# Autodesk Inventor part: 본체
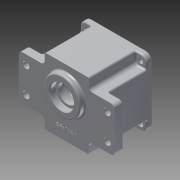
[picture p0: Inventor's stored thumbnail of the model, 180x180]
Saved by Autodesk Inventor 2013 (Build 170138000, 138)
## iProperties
Created: 2015-07
Part Number: 본체
Material: 알루미늄 6061
Document SubType Name: Modeling
Designer: user
Density: 2.71 g/cm^3
Mass: 705.36 g
Surface Area: 672.936 cm^2
Volume: 260.28 cm^3
Author: user
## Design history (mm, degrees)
sketch "스케치1"
  geometry: L1 (65, -30)-(-65, -30); L2 (-65, -30)-(-65, 30); L3 (-65, 30)-(65, 30); L4 (65, 30)-(65, -30); L5 (65, -30)-(-65, 30); L6 (-65, -30)-(65, 30); L7 (45, -45)-(-45, -45); L8 (-45, -45)-(-45, 45); L9 (-45, 45)-(45, 45); L10 (45, 45)-(45, -45); L11 (45, -45)-(-45, 45); L12 (-45, -45)-(45, 45); 1 further point
  constraints: 24 end point, 4 midpoint, 4 parallel, 2 horizontal, 2 perpendicular
  dimensions: "d0" = 130 distance of L2.end L3.end; "d1" = 60 distance of L1.end L2.end; "d2" = 90 distance of L8.end L9.end; "d3" = 90 distance of L7.end L8.end
extrude "돌출1" new body sketch "스케치1" distance "d4" = 12; taper "d5" = 0 deg
sketch "스케치2"
  geometry: L1 (45, -45)-(-45, -45); L2 (-45, -45)-(-45, 45); L3 (-45, 45)-(45, 45); L4 (45, 45)-(45, -45); L5 (45, -45)-(-45, 45); L6 (-45, -45)-(45, 45); 1 further point
  constraints: 12 end point, 2 midpoint, 2 parallel, 1 horizontal, 1 perpendicular
  dimensions: "d6" = 90 distance of L2.end L3.end (derived); "d7" = 90 distance of L1.end L2.end (derived)
extrude "돌출2" join sketch "스케치2" distance "d8" = 58; taper "d9" = 0 deg
sketch "스케치3"
  geometry: L1 (45, 30)-(45, 45) reference; L2 (45, 45)-(-45, 45) reference; L3 (-45, 45)-(-45, 30) reference; L4 (-45, -30)-(-45, -45) reference; L5 (30, -30)-(-30, -30); L6 (-30, -30)-(-30, 30); L7 (-30, 30)-(30, 30); L8 (30, 30)-(30, -30); L9 (30, -30)-(-30, 30); L10 (-30, -30)-(30, 30); L11 (-30, 30)-(-45, 30); L12 (30, 30)-(45, 30); L13 (30, 30)-(30, 45); L14 (-30, 30)-(-30, 45); L15 (-30, 45)-(-45, 45); L16 (-45, 30)-(-45, 45); L17 (30, 45)-(45, 45); L18 (45, 45)-(45, 30); L19 (0, 0)-(41.753, 0); L20 (-30, -30)-(-30, -45); L21 (-30, -30)-(-45, -30); L22 (-45, -30)-(-45, -45); L23 (-30, -45)-(-45, -45); L24 (30, -45)-(45, -45); L25 (30, -30)-(30, -45); L26 (30, -30)-(45, -30); L27 (45, -45)-(45, -30)
  constraints: 46 end point, 6 perpendicular, 2 collinear, 2 midpoint, 2 parallel, 2 point on line, 2 symmetric about line, 1 horizontal
  dimensions: "d10" = 60 distance of L6.end L7.end; "d11" = 60 distance of L5.end L6.end
extrude "돌출3" cut sketch "스케치3" distance "d12" = 63; taper "d13" = 0 deg
sketch "스케치4"
  geometry: L1 (37, -37)-(-37, -37); L2 (-37, -37)-(-37, 37); L3 (-37, 37)-(37, 37); L4 (37, 37)-(37, -37); L5 (37, -37)-(-37, 37); L6 (-37, -37)-(37, 37); C1 r 3.5 at (-37, 37); C2 r 3.5 at (-37, -37); C3 r 3.5 at (37, -37); C4 r 3.5 at (37, 37); 1 further point
  constraints: 12 end point, 4 centre point, 2 midpoint, 2 parallel, 1 coincident, 1 horizontal, 1 perpendicular, 9 other
  dimensions: "d14" = 74 distance of L2.end L3.end; "d15" = 74 distance of L1.end L2.end; "d16" = 7 diameter of C1; "d19" = 360 deg dimension on point (0, 0) C1.centre (derived)
extrude "돌출4" cut sketch "스케치4" distance "d21" = 63; taper "d22" = 0 deg
fillet "모깎기1" dims "d23" = 8
fillet "모깎기2" dims "d24" = 8
sketch "스케치5"
  geometry: C1 r 40 at (0, 0); 1 further point
  constraints: 1 centre point, 1 coincident
  dimensions: "d25" = 80 diameter of C1
extrude "돌출5" cut sketch "스케치5" distance "d26" = 9; taper "d27" = 0 deg
sketch "스케치6"
  geometry: C1 r 40 at (0, 0) reference; C2 r 39 at (0, 0)
  constraints: 1 centre point, 1 coincident
  dimensions: "d28" = 78 diameter of C2
extrude "돌출6" cut sketch "스케치6" distance "d29" = 52; taper "d30" = 0 deg
sketch "스케치7"
  geometry: L1 (-65, -30)-(-30, -30) reference; L2 (0, 0)-(0, 11); C1 r 25 at (0, 11)
  constraints: 2 end point, 1 centre point, 1 coincident, 1 perpendicular
  dimensions: "d31" = 11 distance of L2.start L2.end; "d32" = 50 diameter of C1
extrude "돌출7" join sketch "스케치7" distance "d33" = 7; taper "d34" = 0 deg
sketch "스케치8"
  geometry: C1 r 25 at (0, 0) reference; C2 r 16 at (0, 0); 1 further point
  constraints: 1 centre point, 1 coincident
  dimensions: "d35" = 32 diameter of C2
extrude "돌출8" cut sketch "스케치8" distance "d36" = 8; taper "d37" = 0 deg
sketch "스케치9"
  geometry: L1 (0, 0)-(0, -11); L2 (0, 0)-(0, 20); C1 r 39 at (0, 0) reference; A1 r 20.5 centre (0, -11) between (-7.402, 8.117) and (7.402, 8.117); A2 r 14 centre (0, 20) between (7.402, 8.117) and (-7.402, 8.117)
  constraints: 4 end point, 4 point on circle, 2 centre point, 1 coincident, 1 collinear, 1 vertical
  dimensions: "d38" = 11 distance of L1.start L1.end; "d39" = 41 diameter of A1; "d40" = 20 distance of L1.start L2.end; "d41" = 28 diameter of A2; "d42" = 7.40221 distance from line of A1.end L1; "d43" = 0 distance from line of A2.centre L1
extrude "돌출9" join sketch "스케치9" distance "d44" = 7; taper "d45" = 0 deg
sketch "스케치10"
  geometry: C1 r 16 at (0, 0) reference; C2 r 12.5 at (0, 0); 1 further point
  constraints: 1 centre point, 1 coincident
  dimensions: "d46" = 25 diameter of C2
extrude "돌출10" cut sketch "스케치10" distance "d47" = 5; taper "d48" = 0 deg
sketch "스케치11"
  geometry: C1 r 12.5 at (0, 0) reference; C2 r 17.5 at (0, 0); 1 further point
  constraints: 1 centre point, 1 coincident
  dimensions: "d49" = 35 diameter of C2
extrude "돌출11" cut sketch "스케치11" distance "d50" = 10; taper "d51" = 0 deg
sketch "스케치12"
  geometry: C1 r 11 at (0, 20); A1 r 14 centre (0, 20) between (7.402, 8.117) and (-7.402, 8.117) reference; 1 further point
  constraints: 1 centre point, 1 coincident
  dimensions: "d52" = 22 diameter of C1
extrude "돌출12" cut sketch "스케치12" distance "d53" = 7; taper "d54" = 0 deg
sketch "스케치13"
  geometry: C1 r 11 at (0, 0) reference; C2 r 9.5 at (0, 0); 1 further point
  constraints: 1 centre point, 1 coincident
  dimensions: "d55" = 19 diameter of C2
extrude "돌출13" cut sketch "스케치13" distance "d56" = 1; taper "d57" = 0 deg
sketch "스케치14"
  geometry: L1 (55, -17.5)-(-55, -17.5); L2 (-55, -17.5)-(-55, 17.5); L3 (-55, 17.5)-(55, 17.5); L4 (55, 17.5)-(55, -17.5); L5 (55, -17.5)-(-55, 17.5); L6 (-55, -17.5)-(55, 17.5); C1 r 4.5 at (55, 17.5); C2 r 4.5 at (55, -17.5); C3 r 4.5 at (-55, -17.5); C4 r 4.5 at (-55, 17.5); 1 further point
  constraints: 12 end point, 4 centre point, 4 coincident, 2 midpoint, 2 parallel, 1 horizontal, 1 perpendicular
  dimensions: "d58" = 110 distance of L2.end L3.end; "d59" = 35 distance of L1.end L2.end; "d60" = 9 diameter of C1; "d61" = 9 diameter of C2; "d62" = 9 diameter of C3; "d63" = 9 diameter of C4
extrude "돌출14" cut sketch "스케치14" distance "d64" = 12; taper "d65" = 0 deg
sketch "스케치16"
  geometry: L1 (0, 0)-(35, 0); L2 (0, 0)-(21.92, 21.92); C1 r 39 at (0, 0) reference; A1 r 39 centre (0, 0) between (32.777, 21.134) and (21.134, 32.777); A2 r 35 centre (0, 0) between (21.763, 27.411) and (27.411, 21.763); A3 r 4 centre (24.749, 24.749) between (21.809, 27.462) and (27.462, 21.809); A4 r 3.5 centre (29.836, 19.238) between (32.777, 21.134) and (27.412, 21.762); A5 r 3.5 centre (19.238, 29.836) between (21.762, 27.412) and (21.134, 32.777)
  constraints: 18 point on circle, 5 centre point, 5 tangent, 4 end point, 2 coincident, 1 horizontal
  dimensions: "d78" = 78 diameter of A1; "d79" = 70 diameter of A2; "d80" = 45 deg angle of L2 L1; "d81" = 8 diameter of A3; "d82" = 7 diameter of A4; "d84" = 7 diameter of A5; "d85" = 21.13421 distance from line of A1.start L1
extrude "돌출16" join sketch "스케치16" distance "d86" = 52; taper "d87" = 0 deg
fillet "모깎기3" dims "d91" = 5
fillet "모깎기6" dims "d94" = 2
sketch "스케치17"
  geometry: A1 r 4 centre (24.749, -24.749) between (27.462, -21.809) and (21.809, -27.462) reference; A2 r 4 centre (-24.749, -24.749) between (-21.809, -27.462) and (-27.462, -21.809) reference; A3 r 4 centre (-24.749, 24.749) between (-27.462, 21.809) and (-21.809, 27.462) reference; A4 r 4 centre (24.749, 24.749) between (21.809, 27.462) and (27.462, 21.809) reference
hole "구멍1" sketch "스케치17" at (-24.749, 24.749), (-24.749, -24.749), (24.749, 24.749), (24.749, -24.749) diameter "d96" = 3.459; stored, may be unused: countersink angle "d100" = 90 deg, drill point angle "d102" = 118 deg; dims "d97" = 12, "d98" = 4, "d99" = 2, "d101" = 15
fillet "모깎기8" dims "d103" = 2
fillet "모깎기9" dims "d104" = 3
fillet "모깎기10" dims "d105" = 2
chamfer "모따기1" distance "d106" = 1; stored, may be unused: second distance "d107" = 2, angle "d108" = 45 deg
fillet "모깎기11" dims "d109" = 0.3
fillet "모깎기12" dims "d110" = 2
fillet "모깎기13" dims "d111" = 5
sketch "스케치18"
  geometry: L1 (-30, -45)-(30, -45) reference; 4 further points
  constraints: 1 other
  dimensions: "d114" = 0 horizontal distance of point (0, 0) point (0, -30); "d115" = 15 distance from line of L1 point (0, -30)
feature "엠보싱1" sketch "스케치18" dims "d116" = 0.5, "d117" = 0
fillet "모깎기21" dims "d123" = 2
fillet "모깎기24" dims "d126" = 2
fillet "모깎기26" dims "d128" = 2
fillet "모깎기27" dims "d129" = 2
fillet "모깎기28" dims "d130" = 2
fillet "모깎기29" dims "d131" = 2
chamfer "모따기2" distance "d132" = 1; stored, may be unused: second distance "d133" = 2, angle "d134" = 45 deg
node "솔리드1"
pattern_circular "원형 패턴1" dims angle "d89" = 360 deg
